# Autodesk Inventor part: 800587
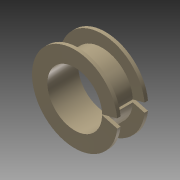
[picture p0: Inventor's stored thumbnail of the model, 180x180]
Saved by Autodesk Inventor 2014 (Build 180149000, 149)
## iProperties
Created: 2007-10
Part Number: 800587
Document SubType Name: Modeling
Designer: RS
Density: 1.13 g/cm^3
Mass: 0.132415 g
Surface Area: 5.13448 cm^2
Volume: 0.117182 cm^3
Material: Nylon-6/6
Description: SPLIT BUSHING 8 MM
Appearance: Wheat
Component Category: Fasteners
Author: RS
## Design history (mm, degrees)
sketch "Sketch1"
  geometry: L1 (0, -3.15)-(0, 3.15) reference; L2 (-1.25, 0)-(7.5, 0) reference; L3 (4, -2.25)-(4, 2.25); L4 (4, 2.25)-(6.25, 2.25); L5 (6.25, 2.25)-(6.25, 1.75); L6 (6.25, 1.75)-(4.5, 1.75); L7 (4.5, 1.75)-(4.5, -1.75); L8 (4.5, -1.75)-(6.25, -1.75); L9 (6.25, -1.75)-(6.25, -2.25); L10 (6.25, -2.25)-(4, -2.25); 2 further points
  constraints: 16 end point, 6 parallel, 2 perpendicular, 1 collinear, 1 midpoint, 1 point on line
  dimensions: "d0" = 8 diameter of L3 L1; "d1" = 9 diameter of L7 L1; "d2" = 12.5 diameter of L5 L1; "d3" = 0.5 distance between parallel lines of L8 L10; "d4" = 3.5 distance between parallel lines of L6 L8; "d5" = 0.5 distance between parallel lines of L4 L6
revolve "Revolution1" sketch "Sketch1" stored, may be unused: angle "d6" = 90 deg
sketch "Sketch2"
  geometry: L1 (-8.75, 0)-(8.75, 0) reference; L2 (0, 8.75)-(0, -8.75) reference; L3 (4, -0.053)-(6.216, -0.647); L4 (4, 0.053)-(6.216, 0.647); A1 r 6.25 centre (0, 0) between (6.216, -0.647) and (6.216, 0.647) reference; A2 r 4 centre (0, 0) between (4, 0.053) and (4, -0.053) reference; A3 r 4 centre (0, 0) between (4, -0.053) and (4, 0.053); A4 r 6.25 centre (0, 0) between (6.216, -0.647) and (6.216, 0.647)
  constraints: 8 point on circle, 4 end point, 2 centre point, 2 coincident
  dimensions: "d8" = 15 deg angle of L3 L1; "d9" = 30 deg angle of L4 L3; "d10" = 2.21673 horizontal distance of L3.start L3.end; "d11" = 2.21673 horizontal distance of L4.start L4.end
extrude "Extrusion1" cut sketch "Sketch2" stored distance "d12" = 10; taper "d13" = 0 deg
body "Solid1"
